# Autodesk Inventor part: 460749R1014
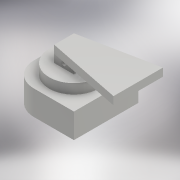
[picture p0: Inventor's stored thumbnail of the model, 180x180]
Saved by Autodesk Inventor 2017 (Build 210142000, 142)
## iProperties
Created: 2016-07
Part Number: 460749R1014
Material: Aluminum 6061
Document SubType Name: Modeling
Designer: Polytech
Density: 2.7 g/cm^3
Appearance: Aluminum - Flat
Mass: 1260.26 g
Surface Area: 611.154 cm^2
Volume: 466.762 cm^3
Author: Polytech
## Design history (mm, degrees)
sketch "Sketch1"
  geometry: C1 r 23 at (0, 0); 1 further point
  constraints: 1 centre point, 1 coincident
  dimensions: "d0" = 46 diameter of C1
extrude "Extrusion1" new body sketch "Sketch1" distance "d1" = 18; taper "d2" = 0 deg
sketch "Sketch2"
  geometry: L1 (-11.75, -48.75)-(48.75, -48.75); L2 (48.75, -48.75)-(48.75, 48.75); L3 (48.75, 48.75)-(-11.75, 48.75); L4 (-48.75, 11.75)-(-48.75, -11.75); L5 (-48.75, -48.75)-(48.75, 48.75); L6 (48.75, -48.75)-(-48.75, 48.75); A1 r 37 centre (-11.75, 11.75) between (-11.75, 48.75) and (-48.75, 11.75); A2 r 37 centre (-11.75, -11.75) between (-48.75, -11.75) and (-11.75, -48.75); 1 further point
  constraints: 12 end point, 4 point on circle, 4 point on line, 4 tangent, 2 centre point, 2 midpoint, 2 parallel, 1 equal radius, 1 horizontal, 1 perpendicular
  dimensions: "d3" = 97.5 distance of L6.end L2.end; "d4" = 97.5 distance of L2.end L1.end; "d5" = 37 radius of A1
extrude "Extrusion2" join sketch "Sketch2" distance "d6" = 37.5; taper "d7" = 0 deg
sketch "Sketch3"
  geometry: C1 r 37.5 at (0, 0); 1 further point
  constraints: 1 centre point, 1 coincident
  dimensions: "d8" = 75 diameter of C1
extrude "Extrusion3" join sketch "Sketch3" distance "d9" = 15; taper "d10" = 0 deg
sketch "Sketch4"
  geometry: L1 (-15, -15)-(15, -15); L2 (15, -15)-(15, 15); L3 (15, 15)-(-15, 15); L4 (-15, 15)-(-15, -15); L5 (-15, -15)-(15, 15); L6 (15, -15)-(-15, 15); 1 further point
  constraints: 12 end point, 2 midpoint, 2 parallel, 1 horizontal, 1 perpendicular
  dimensions: "d11" = 30 distance of L3.end L2.end; "d12" = 30 distance of L2.end L1.end
extrude "Extrusion4" join sketch "Sketch4" distance "d13" = 12; taper "d14" = 0 deg
sketch "Sketch5"
  geometry: L1 (-15, -6)-(15, -6); L2 (15, -6)-(15, 6); L3 (15, 6)-(-15, 6); L4 (-15, 6)-(-15, -6); L5 (-15, -6)-(15, 6); L6 (15, -6)-(-15, 6); 1 further point
  constraints: 12 end point, 2 midpoint, 2 parallel, 1 horizontal, 1 perpendicular
  dimensions: "d15" = 30 distance of L3.end L2.end; "d16" = 12 distance of L2.end L1.end
extrude "Extrusion5" cut sketch "Sketch5" distance "d17" = 12; taper "d18" = 0 deg
sketch "Sketch6"
  geometry: C1 r 3 at (15, 6.229); 1 further point
  constraints: 1 centre point, 1 vertical alignment
  dimensions: "d19" = 3 radius of C1
extrude "Extrusion6" cut sketch "Sketch6" stored distance "d20" = 12; taper "d21" = 0 deg
sketch "Sketch7"
  geometry: L1 (-15, 15)-(-15, -15); L2 (-15, -15)-(97.5, -37.5); L3 (97.5, -37.5)-(97.5, 37.5); L4 (97.5, 37.5)-(-15, 15); 4 further points
  constraints: 8 end point, 2 coincident, 1 horizontal alignment, 1 midpoint, 1 parallel, 1 vertical
  dimensions: "d22" = 75 distance of L2.end L3.end; "d23" = 97.5 distance from line of L3 point (0, 0)
extrude "Extrusion7" join sketch "Sketch7" distance "d24" = 12; taper "d25" = 0 deg
sketch "Sketch8"
  geometry: C1 r 23 at (0, 0); 1 further point
  constraints: 1 centre point, 1 coincident
  dimensions: "d26" = 46 diameter of C1
extrude "Extrusion8" cut sketch "Sketch8" distance "d27" = 24.5; taper "d28" = 0 deg
body "Solid1"
